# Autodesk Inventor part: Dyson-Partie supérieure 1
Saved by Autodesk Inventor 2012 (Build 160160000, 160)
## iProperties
Created: 2012-11
Part Number: Dyson-Partie supérieure 1
Material: Default
Document SubType Name: Modeling
Designer: Administrateur
Density: 1 g/cm^3
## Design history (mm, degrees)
node "Dyson-Partie supérieure 11"
node "Dyson-Partie supérieure 1"
node "Base1"
